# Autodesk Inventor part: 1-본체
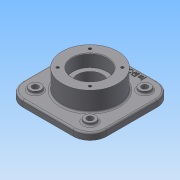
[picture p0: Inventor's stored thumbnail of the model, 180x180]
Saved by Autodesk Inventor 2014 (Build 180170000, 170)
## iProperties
Created: 2015-09
Part Number: 1-본체
Material: Generic
Document SubType Name: Modeling
Designer: study
Density: 1 g/cm^3
Appearance: Default
Author: study
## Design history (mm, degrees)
sketch "스케치1"
  geometry: L1 (75, -75)-(-75, -75); L2 (-75, -75)-(-75, 75); L3 (-75, 75)-(75, 75); L4 (75, 75)-(75, -75); L5 (75, -75)-(-75, 75); L6 (-75, -75)-(75, 75); 1 further point
  constraints: 12 end point, 2 midpoint, 2 parallel, 1 horizontal, 1 perpendicular
  dimensions: "d0" = 150 distance of L2.end L3.end; "d1" = 150 distance of L3.end L1.start
extrude "돌출1" new body sketch "스케치1" distance "d2" = 12; taper "d3" = 0 deg
node "작업 평면1"
sketch "스케치2"
  geometry: C1 r 50 at (0, 0); 1 further point
  constraints: 1 centre point, 1 coincident
  dimensions: "d5" = 100 diameter of C1
extrude "돌출2" join sketch "스케치2" distance "d6" = 70; taper "d7" = 0 deg
hole "구멍1" diameter "d10" = 45; stored, may be unused: countersink angle "d14" = 90 deg, drill point angle "d16" = 118 deg; dims "d8" = 10, "d9" = 10, "d11" = 6, "d12" = 62, "d13" = 22, "d15" = 8
hole "구멍2" diameter "d19" = 45; stored, may be unused: countersink angle "d23" = 90 deg, drill point angle "d25" = 118 deg; dims "d17" = 10, "d18" = 10, "d20" = 6, "d21" = 62, "d22" = 22, "d24" = 8
fillet "모깎기1" dims "d26" = 30
sketch "스케치3"
  geometry: C1 r 50 at (0, 0) reference; C2 r 10 at (-49, 49); C3 r 10 at (49, 49); C4 r 10 at (-49, -49); C5 r 10 at (49, -49)
  constraints: 4 centre point, 3 equal radius
  dimensions: "d27" = 20 diameter of C2; "d28" = 49 horizontal distance of C2.centre C1.centre; "d29" = 49 horizontal distance of C2.centre C1.centre; "d30" = 49 horizontal distance of C3.centre C1.centre; "d31" = 49 horizontal distance of C3.centre C1.centre; "d32" = 49 horizontal distance of C1.centre C4.centre; "d33" = 49 horizontal distance of C1.centre C4.centre; "d34" = 49 horizontal distance of C5.centre C1.centre; "d35" = 49 horizontal distance of C5.centre C1.centre
extrude "돌출3" join sketch "스케치3" distance "d36" = 5; taper "d37" = 0 deg
hole "구멍3" diameter "d40" = 11; stored, may be unused: countersink angle "d44" = 90 deg, drill point angle "d46" = 118 deg; dims "d38" = 10, "d39" = 10, "d41" = 6, "d42" = 62, "d43" = 22, "d45" = 8
hole "구멍4" diameter "d49" = 11; stored, may be unused: countersink angle "d53" = 90 deg, drill point angle "d55" = 118 deg; dims "d47" = 10, "d48" = 10, "d50" = 6, "d51" = 62, "d52" = 22, "d54" = 8
hole "구멍5" diameter "d58" = 11; stored, may be unused: countersink angle "d62" = 90 deg, drill point angle "d64" = 118 deg; dims "d56" = 10, "d57" = 10, "d59" = 6, "d60" = 62, "d61" = 22, "d63" = 8
hole "구멍6" diameter "d67" = 11; stored, may be unused: countersink angle "d71" = 90 deg, drill point angle "d73" = 118 deg; dims "d65" = 10, "d66" = 10, "d68" = 6, "d69" = 62, "d70" = 22, "d72" = 8
sketch "스케치4" dims "d35" = 49
  geometry: L1 (28.991, -28.991)-(-28.991, -28.991); L2 (-28.991, -28.991)-(-28.991, 28.991); L3 (-28.991, 28.991)-(28.991, 28.991); L4 (28.991, 28.991)-(28.991, -28.991); L5 (28.991, -28.991)-(-28.991, 28.991); L6 (-28.991, -28.991)-(28.991, 28.991); C1 r 50 at (0, 0) reference; 4 further points
  constraints: 12 end point, 4 coincident, 2 midpoint, 2 parallel, 2 perpendicular, 1 horizontal
  dimensions: "d74" = 82 distance of L1.start L2.end
hole "구멍7" sketch "스케치4" at (-28.991, 28.991), (28.991, 28.991), (28.991, -28.991), (-28.991, -28.991) diameter "d75" = 4.917; stored, may be unused: countersink angle "d79" = 90 deg, drill point angle "d81" = 118 deg; dims "d35" = 49, "d76" = 10, "d77" = 62, "d78" = 22, "d80" = 13
node "작업 평면2"
sketch "스케치5"
  geometry: C1 r 50 at (0, 0) reference; 1 further point
  constraints: 1 vertical alignment, 1 other
  dimensions: "d82" = 65 distance of point (0, 65) C1.centre
feature "엠보싱1" sketch "스케치5" dims "d0" = 150, "d1" = 150, "d26" = 30, "d83" = 1, "d84" = 0
fillet "모깎기2" dims "d85" = 0.3
chamfer "모따기1" distance "d86" = 1; stored, may be unused: second distance "d87" = 2, angle "d88" = 45 deg
fillet "모깎기3" dims "d89" = 3
node "솔리드1"
mirror "대칭1"
other parameters: "d4" = 23
